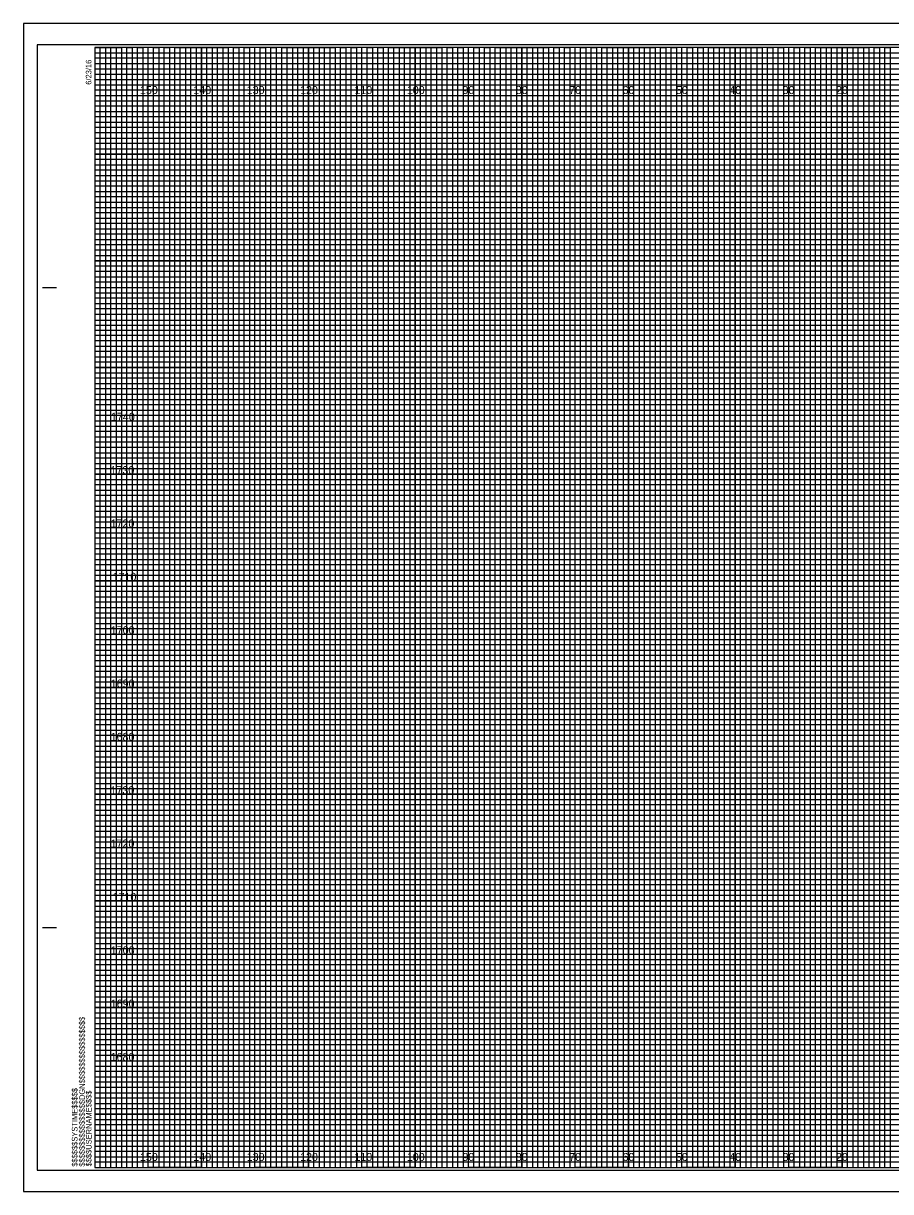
# Model space of a CAD drawing. Extents: x 185 to 522, y -7 to 872.
# Drawn here: x 184.8 to 347.3, y 213.5 to 432.5 of the extents above; entities that cross this region are included whole.
import ezdxf

# ---------------------------------------------------------------- set-up
doc = ezdxf.new("R2010")
doc.units = 0
for name, color, linetype in [('Raster_Level_0', 7, 'Continuous'), ('Scratch_Level_3', 7, 'Continuous'), ('Sheet Cross Section CELL', 7, 'Continuous'), ('Sheet Cross Section Grid Major CELL', 7, 'Continuous'), ('Sheet Cross Section Grid Middle CELL', 7, 'Continuous'), ('Sheet Cross Section Grid Minor 1 CELL', 7, 'Continuous'), ('Sheet Cross Section Grid Minor 2 CELL', 7, 'Continuous'), ('Sheet Cutting Line CELL', 7, 'Continuous'), ('Sheet DOT Grid CELL', 7, 'Continuous'), ('Sheet Plot Border Inside CELL', 7, 'Continuous'), ('Sheet Plot Border Outside CELL', 7, 'Continuous')]:
    doc.layers.add(name, color=color, linetype=linetype)

msp = doc.modelspace()

# ---------------------------------------------------------------- linework, layer by layer
at = {"layer": 'Sheet Cross Section CELL'}
for p, q in [((188.44, 382.95), (190.94, 382.95)), ((188.54, 382.95), (191.04, 382.95)), ((188.44, 262.95), (190.94, 262.95)), ((188.54, 262.95), (191.04, 262.95)), ((198.24, 217.95), (198.24, 217.95)), ((198.24, 217.95), (198.24, 217.95)), ((198.24, 217.95), (198.24, 217.95)), ((198.24, 217.95), (198.24, 217.95)), ((198.24, 217.95), (198.24, 217.95)), ((198.24, 217.95), (198.24, 217.95)), ((198.24, 217.95), (198.24, 217.95))]:
    msp.add_line(p, q, dxfattribs=at)
msp.add_lwpolyline([(518.24, 427.95), (198.24, 427.95), (198.24, 217.95), (518.24, 217.95)], close=True, dxfattribs=at)
at = {"layer": 'Sheet Cross Section Grid Major CELL'}
for p, q in [((208.24, 427.95), (198.24, 427.95)), ((208.24, 217.95), (208.24, 427.95)), ((228.24, 427.95), (218.24, 427.95)), ((218.24, 427.95), (218.24, 217.95)), ((228.24, 217.95), (228.24, 427.95)), ((248.24, 427.95), (238.24, 427.95)), ((238.24, 427.95), (238.24, 217.95)), ((248.24, 217.95), (248.24, 427.95)), ((268.24, 427.95), (258.24, 427.95)), ((258.24, 427.95), (258.24, 217.95)), ((268.24, 217.95), (268.24, 427.95)), ((288.24, 427.95), (278.24, 427.95)), ((278.24, 427.95), (278.24, 217.95)), ((288.24, 217.95), (288.24, 427.95)), ((308.24, 427.95), (298.24, 427.95)), ((298.24, 427.95), (298.24, 217.95)), ((308.24, 217.95), (308.24, 427.95)), ((328.24, 427.95), (318.24, 427.95)), ((318.24, 427.95), (318.24, 217.95)), ((328.24, 217.95), (328.24, 427.95)), ((348.24, 427.95), (338.24, 427.95)), ((338.24, 427.95), (338.24, 217.95)), ((218.24, 217.95), (208.24, 217.95)), ((238.24, 217.95), (228.24, 217.95)), ((258.24, 217.95), (248.24, 217.95)), ((278.24, 217.95), (268.24, 217.95)), ((298.24, 217.95), (288.24, 217.95)), ((318.24, 217.95), (308.24, 217.95)), ((338.24, 217.95), (328.24, 217.95))]:
    msp.add_line(p, q, dxfattribs=at)
for points in [[(198.24, 417.95), (518.24, 417.95), (518.24, 407.95), (198.24, 407.95)], [(198.24, 397.95), (518.24, 397.95), (518.24, 387.95), (198.24, 387.95)], [(198.24, 377.95), (518.24, 377.95), (518.24, 367.95), (198.24, 367.95)], [(198.24, 357.95), (518.24, 357.95), (518.24, 347.95), (198.24, 347.95)], [(198.24, 337.95), (518.24, 337.95), (518.24, 327.95), (198.24, 327.95)], [(198.24, 317.95), (518.24, 317.95), (518.24, 307.95), (198.24, 307.95)], [(198.24, 297.95), (518.24, 297.95), (518.24, 287.95), (198.24, 287.95)], [(198.24, 277.95), (518.24, 277.95), (518.24, 267.95), (198.24, 267.95)], [(198.24, 257.95), (518.24, 257.95), (518.24, 247.95), (198.24, 247.95)], [(198.24, 237.95), (518.24, 237.95), (518.24, 227.95), (198.24, 227.95)]]:
    msp.add_lwpolyline(points, dxfattribs=at)
at = {"layer": 'Sheet Cross Section Grid Middle CELL'}
for points in [[(198.24, 427.95), (203.24, 427.95), (203.24, 217.95), (213.24, 217.95), (213.24, 427.95), (223.24, 427.95), (223.24, 217.95), (233.24, 217.95), (233.24, 427.95), (243.24, 427.95), (243.24, 217.95), (253.24, 217.95), (253.24, 427.95), (263.24, 427.95), (263.24, 217.95), (273.24, 217.95), (273.24, 427.95), (283.24, 427.95), (283.24, 217.95), (293.24, 217.95), (293.24, 427.95), (303.24, 427.95), (303.24, 217.95), (313.24, 217.95), (313.24, 427.95), (323.24, 427.95), (323.24, 217.95), (333.24, 217.95), (333.24, 427.95), (343.24, 427.95), (343.24, 217.95), (353.24, 217.95)], [(198.24, 422.95), (473.24, 422.95)], [(198.24, 402.95), (518.24, 402.95), (518.24, 412.95), (198.24, 412.95)], [(198.24, 382.95), (518.24, 382.95), (518.24, 392.95), (198.24, 392.95)], [(198.24, 362.95), (518.24, 362.95), (518.24, 372.95), (198.24, 372.95)], [(198.24, 342.95), (518.24, 342.95), (518.24, 352.95), (198.24, 352.95)], [(198.24, 322.95), (518.24, 322.95), (518.24, 332.95), (198.24, 332.95)], [(198.24, 302.95), (518.24, 302.95), (518.24, 312.95), (198.24, 312.95)], [(198.24, 282.95), (518.24, 282.95), (518.24, 292.95), (198.24, 292.95)], [(198.24, 262.95), (518.24, 262.95), (518.24, 272.95), (198.24, 272.95)], [(198.24, 242.95), (518.24, 242.95), (518.24, 252.95), (198.24, 252.95)], [(198.24, 222.95), (518.24, 222.95), (518.24, 232.95), (198.24, 232.95)]]:
    msp.add_lwpolyline(points, dxfattribs=at)
at = {"layer": 'Sheet Cross Section Grid Minor 1 CELL'}
for p, q in [((198.24, 426.95), (458.24, 426.95)), ((458.24, 425.93), (198.24, 425.93)), ((198.24, 425.93), (198.24, 424.95)), ((198.24, 424.95), (458.24, 424.95)), ((458.24, 423.84), (198.24, 423.84)), ((198.24, 423.84), (198.24, 421.95)), ((198.24, 421.95), (518.24, 421.95))]:
    msp.add_line(p, q, dxfattribs=at)
for points in [[(198.24, 420.95), (468.24, 420.95), (518.24, 420.95), (518.24, 419.95), (198.24, 419.95)], [(198.24, 418.95), (518.24, 418.95), (518.24, 416.95), (198.24, 416.95)], [(198.24, 415.95), (518.24, 415.95), (518.24, 414.95), (198.24, 414.93)], [(198.24, 413.95), (518.24, 413.95), (518.24, 411.95), (198.24, 411.95)], [(198.24, 410.95), (518.24, 410.95), (518.24, 409.95), (198.24, 409.95)], [(198.24, 408.95), (518.24, 408.95), (518.24, 406.95), (198.24, 406.95)], [(198.24, 405.95), (518.24, 405.95), (518.24, 404.95), (198.24, 404.95)], [(198.24, 403.95), (518.24, 403.95), (518.24, 401.95), (198.24, 401.95)], [(198.24, 400.95), (518.24, 400.95), (518.24, 399.95), (198.24, 399.95)], [(198.24, 398.95), (518.24, 398.95), (518.24, 396.95), (198.24, 396.95)], [(198.24, 395.95), (518.24, 395.95), (518.24, 394.95), (198.24, 394.95)], [(198.24, 393.95), (518.24, 393.95), (518.24, 391.9), (518.24, 390.95), (518.24, 389.95), (198.24, 389.95)], [(198.24, 391.95), (518.24, 391.95), (518.24, 390.95), (198.24, 390.95)], [(198.24, 388.95), (518.24, 388.95), (518.24, 386.95), (198.24, 386.98)], [(198.24, 386.98), (518.24, 386.95), (518.24, 385.95), (198.24, 385.95)], [(198.24, 384.95), (518.24, 384.95), (518.24, 383.95), (198.24, 383.95)], [(198.24, 381.95), (518.24, 381.95), (518.24, 380.95), (198.24, 380.95)], [(198.24, 379.95), (518.24, 379.95), (518.24, 378.95), (198.24, 378.95)], [(198.17, 376.84), (518.24, 376.84), (518.24, 375.83), (198.17, 375.83)], [(198.24, 374.95), (518.24, 374.95), (518.24, 373.95), (198.24, 373.95)], [(198.24, 371.95), (518.24, 371.95), (518.24, 370.95), (198.24, 370.95)], [(198.24, 369.95), (518.24, 369.95), (518.24, 368.95), (198.24, 368.95)], [(198.24, 366.95), (518.24, 366.95), (518.24, 365.95), (198.24, 365.95)], [(198.24, 364.95), (518.24, 364.95), (518.24, 363.95), (198.24, 363.95)], [(198.24, 361.95), (518.24, 361.95), (518.24, 360.95), (198.24, 360.95)], [(198.24, 359.95), (518.24, 359.95), (518.24, 358.95), (198.24, 358.95)], [(198.24, 356.95), (518.24, 356.95), (518.23, 355.93), (198.24, 355.95)], [(198.24, 354.95), (518.24, 354.95), (518.24, 353.95), (198.24, 353.95)], [(198.24, 351.95), (518.24, 351.95), (518.24, 350.95), (198.24, 350.95)], [(198.24, 349.95), (518.24, 349.95), (518.24, 348.95), (198.24, 348.95)], [(198.24, 346.95), (518.24, 346.95), (518.24, 345.95), (198.24, 345.95)], [(198.24, 344.95), (518.24, 344.95), (518.24, 343.95), (198.24, 343.95)], [(198.24, 341.95), (518.24, 341.95), (518.24, 340.95), (198.24, 340.95)], [(198.24, 339.95), (518.24, 339.95), (518.24, 338.95), (198.24, 338.95)], [(198.24, 336.95), (518.24, 336.95), (518.24, 335.95), (198.24, 335.95)], [(198.24, 334.94), (518.31, 334.86), (518.24, 333.95), (198.24, 333.95)], [(198.24, 331.95), (518.24, 331.95), (518.24, 330.95), (198.24, 330.95)], [(198.24, 329.95), (518.24, 329.95), (518.24, 328.95), (198.24, 328.95)], [(198.24, 326.95), (518.24, 326.95), (518.24, 325.95), (198.24, 325.95)], [(198.24, 324.95), (518.24, 324.95), (518.24, 323.95), (198.24, 323.95)], [(198.24, 321.95), (518.24, 321.95), (518.24, 320.95), (198.24, 320.95)], [(198.24, 319.95), (518.24, 319.95), (518.24, 318.95), (198.24, 318.95)], [(198.24, 316.95), (518.24, 316.95), (518.24, 315.95), (198.24, 315.95)], [(198.24, 314.95), (518.24, 314.95), (518.24, 313.95), (198.24, 313.95)], [(198.24, 311.95), (518.24, 311.95), (518.24, 310.95), (198.24, 310.95)], [(198.24, 309.95), (518.24, 309.95), (518.24, 308.95), (198.24, 308.95)], [(198.24, 306.95), (518.24, 306.95), (518.24, 305.95), (198.24, 305.95)], [(198.24, 304.95), (518.24, 304.95), (518.24, 303.95), (198.24, 303.95)], [(198.24, 301.95), (518.24, 301.95), (518.24, 300.95), (198.24, 300.95)], [(198.24, 299.95), (518.24, 299.95), (518.24, 298.95), (198.24, 298.95)], [(198.24, 296.95), (518.24, 296.95), (518.23, 295.93), (198.24, 295.95)], [(198.24, 294.95), (518.24, 294.95), (518.24, 293.95), (198.24, 293.95)], [(198.24, 291.95), (518.24, 291.95), (518.24, 290.95), (198.24, 290.95)], [(198.24, 289.95), (518.24, 289.95), (518.24, 288.95), (198.24, 288.95)], [(198.24, 286.95), (518.24, 286.95), (518.24, 285.95), (198.24, 285.95)], [(198.24, 284.95), (518.24, 284.95), (518.24, 283.95), (198.24, 283.95)], [(198.24, 281.95), (518.24, 281.95), (518.24, 280.95), (198.24, 280.95)], [(198.24, 279.95), (518.24, 279.95), (518.24, 278.95), (198.24, 278.95)], [(198.24, 276.95), (518.24, 276.95), (518.24, 275.95), (198.24, 275.95)], [(198.24, 274.94), (518.31, 274.86), (518.24, 273.95), (198.24, 273.95)], [(198.24, 271.95), (518.24, 271.95), (518.24, 270.95), (198.24, 270.95)], [(198.24, 269.95), (518.24, 269.95), (518.24, 268.95), (198.24, 268.95)], [(198.24, 266.95), (518.24, 266.95), (518.24, 265.95), (198.24, 265.95)], [(198.24, 264.95), (518.24, 264.95), (518.24, 263.95), (198.24, 263.95)], [(198.24, 261.95), (518.24, 261.95), (518.24, 260.95), (198.24, 260.95)], [(198.24, 259.95), (518.24, 259.95), (518.24, 258.95), (198.24, 258.95)], [(198.24, 256.95), (518.24, 256.95), (518.24, 255.95), (198.24, 255.95)], [(198.24, 254.95), (518.24, 254.95), (518.24, 253.95), (198.24, 253.95)], [(198.24, 251.95), (518.24, 251.95), (518.24, 250.95), (198.24, 250.95)], [(198.24, 249.95), (518.24, 249.95), (518.24, 248.95), (198.24, 248.95)], [(198.24, 246.95), (518.24, 246.95), (518.24, 245.95), (198.24, 245.95)], [(198.24, 244.95), (518.24, 244.95), (518.24, 243.95), (198.24, 243.95)], [(198.24, 241.95), (518.24, 241.95), (518.24, 240.95), (198.24, 240.95)], [(198.24, 239.95), (518.24, 239.95), (518.24, 238.95), (198.24, 238.95)], [(198.24, 236.95), (518.24, 236.95), (518.24, 235.95), (198.24, 235.95)], [(198.24, 234.95), (518.24, 234.95), (518.24, 233.95), (198.24, 233.95)], [(198.24, 231.95), (518.24, 231.95), (518.24, 230.95), (198.24, 230.95)], [(198.24, 229.95), (518.24, 229.95), (518.24, 228.95), (198.24, 228.95)], [(198.24, 226.95), (518.24, 226.95), (518.24, 225.95), (198.24, 225.95)], [(198.24, 224.95), (518.24, 224.95), (518.24, 223.95), (198.24, 223.95)], [(198.24, 221.95), (518.24, 221.95), (518.24, 220.95), (198.24, 220.95)], [(198.24, 219.95), (518.24, 219.95), (518.24, 218.95), (198.24, 218.95)]]:
    msp.add_lwpolyline(points, dxfattribs=at)
at = {"layer": 'Sheet Cross Section Grid Minor 2 CELL'}
for points in [[(198.24, 217.95), (199.24, 217.95), (199.24, 427.95), (200.24, 427.95), (200.24, 217.95)], [(200.24, 217.95), (201.24, 217.95), (201.24, 427.95), (202.24, 427.95), (202.24, 217.95)], [(203.24, 217.95), (204.24, 217.95), (204.24, 427.95), (205.24, 427.95), (205.24, 217.95)], [(205.24, 217.95), (206.24, 217.95), (206.24, 427.95), (207.24, 427.95), (207.24, 217.95)], [(208.24, 217.95), (209.24, 217.95), (209.24, 427.95), (210.24, 427.95), (210.24, 217.95)], [(210.24, 217.95), (211.24, 217.95), (211.24, 427.95), (212.24, 427.95), (212.24, 217.95)], [(213.24, 217.95), (214.24, 217.95), (214.24, 427.95), (215.24, 427.95), (215.24, 217.95)], [(215.24, 217.95), (216.24, 217.95), (216.24, 427.95), (217.24, 427.95), (217.24, 217.95)], [(218.24, 217.95), (219.24, 217.95), (219.24, 427.95), (220.24, 427.95), (220.24, 217.95)], [(220.24, 217.95), (221.24, 217.95), (221.24, 427.95), (222.24, 427.95), (222.24, 217.95)], [(223.24, 217.95), (224.24, 217.95), (224.24, 427.95), (225.24, 427.95), (225.24, 217.95)], [(225.24, 217.95), (226.24, 217.95), (226.24, 427.95), (227.24, 427.95), (227.24, 217.95)], [(228.24, 217.95), (229.24, 217.95), (229.24, 427.95), (230.24, 427.95), (230.24, 217.95)], [(230.24, 217.95), (231.24, 217.95), (231.24, 427.95), (232.24, 427.95), (232.24, 217.95)], [(233.24, 217.95), (234.24, 217.95), (234.24, 427.95), (235.24, 427.95), (235.24, 217.95)], [(235.24, 217.95), (236.24, 217.95), (236.24, 427.95), (237.24, 427.95), (237.24, 217.95)], [(238.24, 217.95), (239.24, 217.95), (239.24, 427.95), (240.24, 427.95), (240.24, 217.95)], [(240.24, 217.95), (241.24, 217.95), (241.24, 427.95), (242.24, 427.95), (242.24, 217.95)], [(243.24, 217.95), (244.24, 217.95), (244.24, 427.95), (245.24, 427.95), (245.24, 217.95)], [(245.24, 217.95), (246.24, 217.95), (246.24, 427.95), (247.24, 427.95), (247.24, 217.95)], [(248.24, 217.95), (249.24, 217.95), (249.24, 427.95), (250.24, 427.95), (250.24, 217.95)], [(250.24, 217.95), (251.24, 217.95), (251.24, 427.95), (252.24, 427.95), (252.24, 217.95)], [(253.24, 217.95), (254.24, 217.95), (254.24, 427.95), (255.24, 427.95), (255.24, 217.95)], [(255.24, 217.95), (256.24, 217.95), (256.24, 427.95), (257.24, 427.95), (257.24, 217.95)], [(258.24, 217.95), (259.24, 217.95), (259.24, 427.95), (260.24, 427.95), (260.24, 217.95)], [(260.24, 217.95), (261.24, 217.95), (261.24, 427.95), (262.24, 427.95), (262.24, 217.95)], [(263.24, 217.95), (264.24, 217.95), (264.24, 427.95), (265.24, 427.95), (265.24, 217.95)], [(265.24, 217.95), (266.24, 217.95), (266.24, 427.95), (267.24, 427.95), (267.24, 217.95)], [(268.24, 217.95), (269.24, 217.95), (269.24, 427.95), (270.24, 427.95), (270.24, 217.95)], [(270.24, 217.95), (271.24, 217.95), (271.24, 427.95), (272.24, 427.95), (272.24, 217.95)], [(273.24, 217.95), (274.24, 217.95), (274.24, 427.95), (275.24, 427.95), (275.24, 217.95)], [(275.24, 217.95), (276.24, 217.95), (276.24, 427.95), (277.24, 427.95), (277.24, 217.95)], [(278.24, 217.95), (279.24, 217.95), (279.24, 427.95), (280.24, 427.95), (280.24, 217.95)], [(280.24, 217.95), (281.24, 217.95), (281.24, 427.95), (282.24, 427.95), (282.24, 217.95)], [(283.24, 217.95), (284.24, 217.95), (284.24, 427.95), (285.24, 427.95), (285.24, 217.95)], [(285.24, 217.95), (286.24, 217.95), (286.24, 427.95), (287.24, 427.95), (287.24, 217.95)], [(288.24, 217.95), (289.24, 217.95), (289.24, 427.95), (290.24, 427.95), (290.24, 217.95)], [(290.24, 217.95), (291.24, 217.95), (291.24, 427.95), (292.24, 427.95), (292.24, 217.95)], [(293.24, 217.95), (294.24, 217.95), (294.24, 427.95), (295.24, 427.95), (295.24, 217.95)], [(295.24, 217.95), (296.24, 217.95), (296.24, 427.95), (297.24, 427.95), (297.24, 217.95)], [(298.24, 217.95), (299.24, 217.95), (299.24, 427.95), (300.24, 427.95), (300.24, 217.95)], [(300.24, 217.95), (301.24, 217.95), (301.24, 427.95), (302.24, 427.95), (302.24, 217.95)], [(303.24, 217.95), (304.24, 217.95), (304.24, 427.95), (305.24, 427.95), (305.24, 217.95)], [(305.24, 217.95), (306.24, 217.95), (306.24, 427.95), (307.24, 427.95), (307.24, 217.95)], [(308.24, 217.95), (309.24, 217.95), (309.24, 427.95), (310.24, 427.95), (310.24, 217.95)], [(310.24, 217.95), (311.24, 217.95), (311.24, 427.95), (312.24, 427.95), (312.24, 217.95)], [(313.24, 217.95), (314.24, 217.95), (314.24, 427.95), (315.24, 427.95), (315.24, 217.95)], [(315.24, 217.95), (316.24, 217.95), (316.24, 427.95), (317.24, 427.95), (317.24, 217.95)], [(318.24, 217.95), (319.24, 217.95), (319.24, 427.95), (320.24, 427.95), (320.24, 217.95)], [(320.24, 217.95), (321.24, 217.95), (321.24, 427.95), (322.24, 427.95), (322.24, 217.95)], [(323.24, 217.95), (324.24, 217.95), (324.24, 427.95), (325.24, 427.95), (325.24, 217.95)], [(325.24, 217.95), (326.24, 217.95), (326.24, 427.95), (327.24, 427.95), (327.24, 217.95)], [(328.24, 217.95), (329.24, 217.95), (329.24, 427.95), (330.24, 427.95), (330.24, 217.95)], [(330.24, 217.95), (331.24, 217.95), (331.24, 427.95), (332.24, 427.95), (332.24, 217.95)], [(333.24, 217.95), (334.24, 217.95), (334.24, 427.95), (335.24, 427.95), (335.24, 217.95)], [(335.24, 217.95), (336.24, 217.95), (336.24, 427.95), (337.24, 427.95), (337.24, 217.95)], [(338.24, 217.95), (339.24, 217.95), (339.24, 427.95), (340.24, 427.95), (340.24, 217.95)], [(340.24, 217.95), (341.24, 217.95), (341.24, 427.95), (342.24, 427.95), (342.24, 217.95)], [(343.24, 217.95), (344.24, 217.95), (344.24, 427.95), (345.24, 427.95), (345.24, 217.95)], [(345.24, 217.95), (346.24, 217.95), (346.24, 427.95), (347.24, 427.95), (347.24, 217.95)]]:
    msp.add_lwpolyline(points, dxfattribs=at)
at = {"layer": 'Sheet Cutting Line CELL'}
for p, q in [((521.54, 432.45), (184.84, 432.45)), ((184.84, 432.45), (184.84, 213.45)), ((184.84, 213.45), (521.54, 213.45))]:
    msp.add_line(p, q, dxfattribs=at)
at = {"layer": 'Sheet DOT Grid CELL'}
for p, q in [((208.24, 217.95), (208.24, 427.95)), ((218.24, 217.95), (218.24, 427.95)), ((228.24, 217.95), (228.24, 427.95)), ((238.24, 217.95), (238.24, 427.95)), ((248.24, 217.95), (248.24, 427.95)), ((258.24, 217.95), (258.24, 427.95)), ((268.24, 217.95), (268.24, 427.95)), ((278.24, 217.95), (278.24, 427.95)), ((288.24, 217.95), (288.24, 427.95)), ((298.24, 217.95), (298.24, 427.95)), ((308.24, 217.95), (308.24, 427.95)), ((318.24, 217.95), (318.24, 427.95)), ((328.24, 217.95), (328.24, 427.95)), ((338.24, 217.95), (338.24, 427.95)), ((198.24, 417.95), (518.24, 417.95)), ((198.24, 407.95), (518.24, 407.95)), ((198.24, 397.95), (518.24, 397.95)), ((198.24, 387.95), (518.24, 387.95)), ((198.24, 377.95), (518.24, 377.95)), ((198.24, 367.95), (518.24, 367.95)), ((198.24, 357.95), (518.24, 357.95)), ((198.24, 347.95), (518.24, 347.95)), ((198.24, 337.95), (518.24, 337.95)), ((198.24, 327.95), (518.24, 327.95)), ((198.24, 317.95), (518.24, 317.95)), ((198.24, 307.95), (518.24, 307.95)), ((198.24, 297.95), (518.24, 297.95)), ((198.24, 287.95), (518.24, 287.95)), ((198.24, 277.95), (518.24, 277.95)), ((198.24, 267.95), (518.24, 267.95)), ((198.24, 257.95), (518.24, 257.95)), ((198.24, 247.95), (518.24, 247.95)), ((198.24, 237.95), (518.24, 237.95)), ((198.24, 227.95), (518.24, 227.95))]:
    msp.add_line(p, q, dxfattribs=at)
at = {"layer": 'Sheet Plot Border Inside CELL'}
msp.add_lwpolyline([(187.44, 217.45), (520.64, 217.45), (520.64, 428.45), (187.44, 428.45)], close=True, dxfattribs=at)
at = {"layer": 'Sheet Plot Border Outside CELL'}
msp.add_lwpolyline([(184.84, 213.45), (521.54, 213.45), (521.54, 432.45), (184.84, 432.45)], close=True, dxfattribs=at)

# ---------------------------------------------------------------- texts
at = {"layer": 'Raster_Level_0'}
for s, p in [('150', (206.69, 419.2)), ('140', (216.69, 419.2)), ('130', (226.69, 419.2)), ('120', (236.69, 419.2)), ('110', (246.87, 419.2)), ('100', (256.69, 419.2)), ('90', (267.1, 419.2)), ('80', (277.1, 419.2)), ('70', (287.1, 419.2)), ('60', (297.1, 419.2)), ('50', (307.1, 419.2)), ('40', (317.1, 419.2)), ('30', (327.1, 419.2)), ('20', (337.1, 419.2)), ('150', (206.69, 219.2)), ('140', (216.69, 219.2)), ('130', (226.69, 219.2)), ('120', (236.69, 219.2)), ('110', (246.87, 219.2)), ('100', (256.69, 219.2)), ('90', (267.1, 219.2)), ('80', (277.1, 219.2)), ('70', (287.1, 219.2)), ('60', (297.1, 219.2)), ('50', (307.1, 219.2)), ('40', (317.1, 219.2)), ('30', (327.1, 219.2)), ('20', (337.1, 219.2))]:
    msp.add_text(s, height=1.5, dxfattribs=at).set_placement(p)
at = {"layer": 'Scratch_Level_3'}
for s, p in [('1740', (201.25, 357.95)), ('1730', (201.17, 347.95)), ('1720', (201.18, 337.95)), ('1710', (201.55, 327.95)), ('1700', (201.22, 317.95)), ('1690', (201.21, 307.95)), ('1680', (201.19, 297.95)), ('1730', (201.17, 287.95)), ('1720', (201.18, 277.95)), ('1710', (201.55, 267.95)), ('1700', (201.22, 257.95)), ('1690', (201.21, 247.95)), ('1680', (201.19, 237.95))]:
    msp.add_text(s, height=1.5, dxfattribs=at).set_placement(p)
at = {"layer": 'Sheet Cross Section CELL'}
for s, p in [('6/23/16', (197.59, 420.95)), ('$$$$$$$$$$$$$$$$DGN$$$$$$$$$$$$$$$$', (196.36, 218.13)), ('$$$$$$SYSTIME$$$$$', (194.98, 218.13)), ('$$$$USERNAME$$$$', (197.62, 218.18))]:
    msp.add_text(s, height=1.05, rotation=90, dxfattribs=at).set_placement(p)

doc.saveas('drawing.dxf')
